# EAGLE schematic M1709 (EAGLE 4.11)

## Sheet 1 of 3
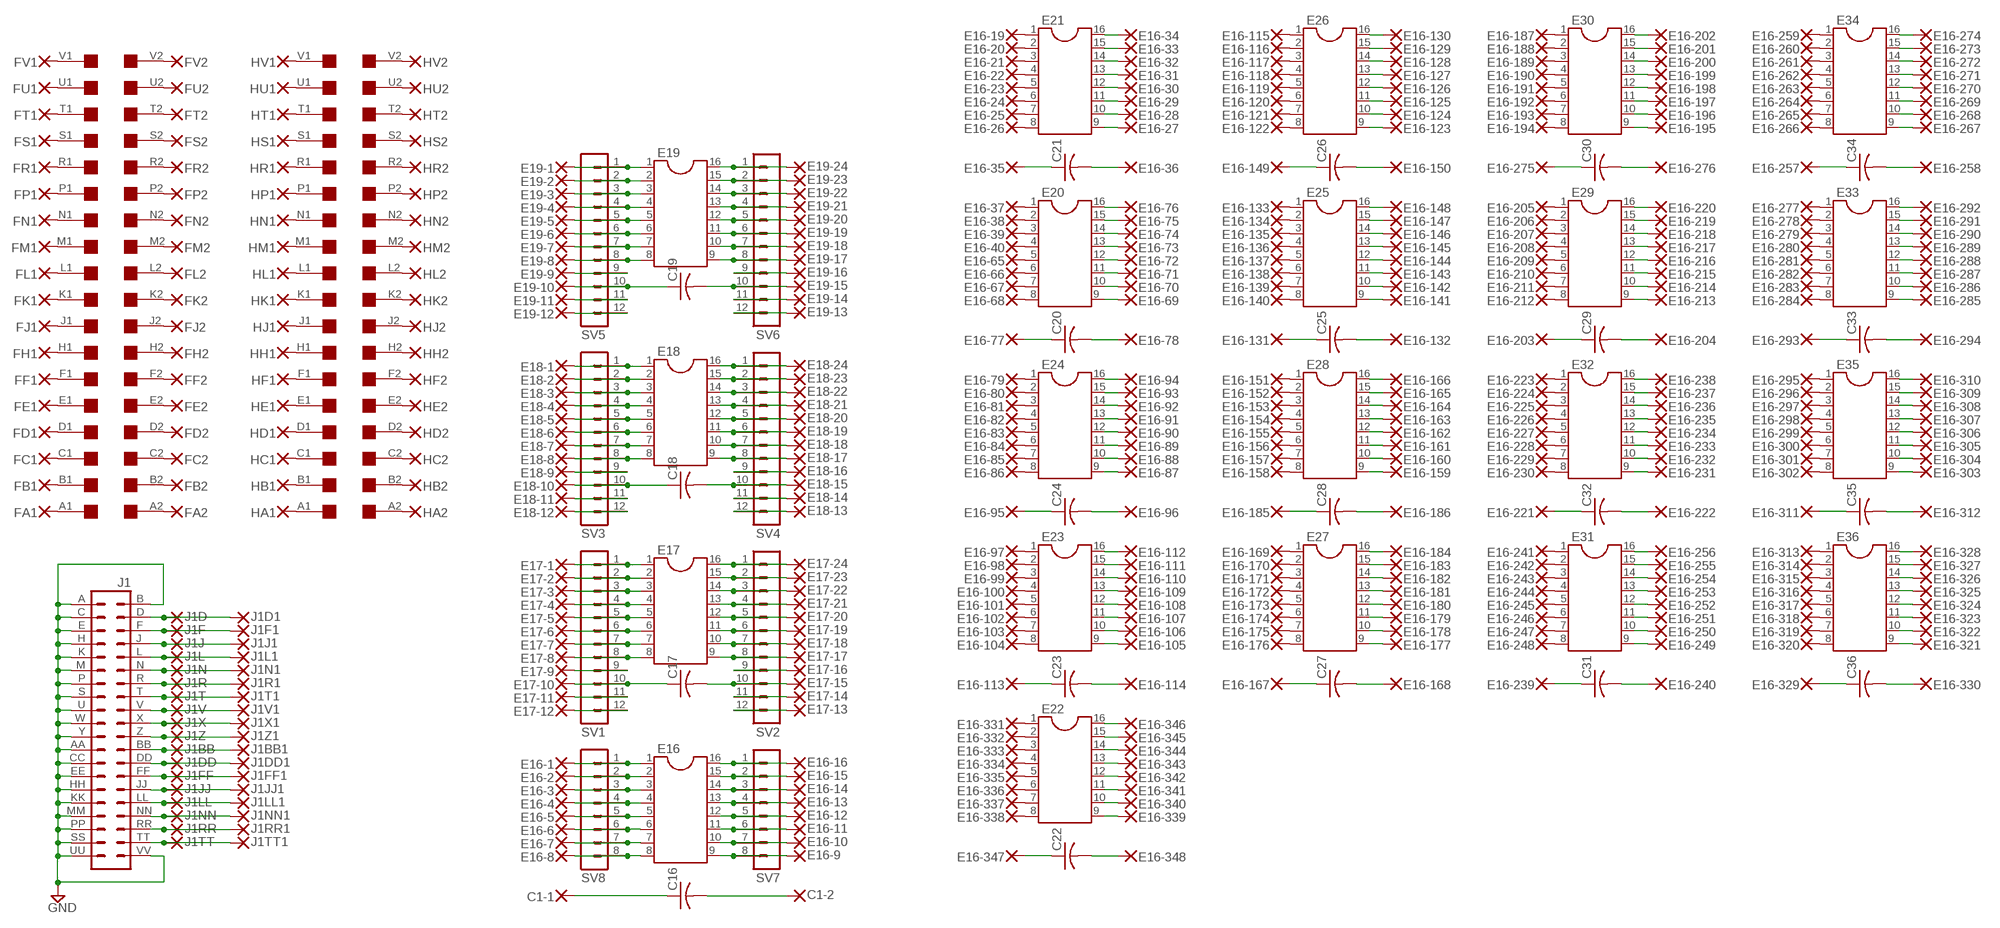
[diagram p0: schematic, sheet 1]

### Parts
C1-1  1,6/0,8  [1,6/0,8]
C1-2  1,6/0,8  [1,6/0,8]
C16  C-US075-032X103  [C075-032X103]
C17  C-US075-032X103  [C075-032X103]
C18  C-US075-032X103  [C075-032X103]
C19  C-US075-032X103  [C075-032X103]
C20  C-US075-032X103  [C075-032X103]
C21  C-US075-032X103  [C075-032X103]
C22  C-US075-032X103  [C075-032X103]
C23  C-US075-032X103  [C075-032X103]
C24  C-US075-032X103  [C075-032X103]
C25  C-US075-032X103  [C075-032X103]
C26  C-US075-032X103  [C075-032X103]
C27  C-US075-032X103  [C075-032X103]
C28  C-US075-032X103  [C075-032X103]
C29  C-US075-032X103  [C075-032X103]
C30  C-US075-032X103  [C075-032X103]
C31  C-US075-032X103  [C075-032X103]
C32  C-US075-032X103  [C075-032X103]
C33  C-US075-032X103  [C075-032X103]
C34  C-US075-032X103  [C075-032X103]
C35  C-US075-032X103  [C075-032X103]
C36  C-US075-032X103  [C075-032X103]
E16  DIL16  [DIL16]
E16-1  1,6/0,8  [1,6/0,8]
E16-2  1,6/0,8  [1,6/0,8]
E16-3  1,6/0,8  [1,6/0,8]
E16-4  1,6/0,8  [1,6/0,8]
E16-5  1,6/0,8  [1,6/0,8]
E16-6  1,6/0,8  [1,6/0,8]
E16-7  1,6/0,8  [1,6/0,8]
E16-8  1,6/0,8  [1,6/0,8]
E16-9  1,6/0,8  [1,6/0,8]
E16-10  1,6/0,8  [1,6/0,8]
E16-11  1,6/0,8  [1,6/0,8]
E16-12  1,6/0,8  [1,6/0,8]
E16-13  1,6/0,8  [1,6/0,8]
E16-14  1,6/0,8  [1,6/0,8]
E16-15  1,6/0,8  [1,6/0,8]
E16-16  1,6/0,8  [1,6/0,8]
E16-19  2,54/0,8  [2,54/0,8]
E16-20  2,54/0,8  [2,54/0,8]
E16-21  2,54/0,8  [2,54/0,8]
E16-22  2,54/0,8  [2,54/0,8]
E16-23  2,54/0,8  [2,54/0,8]
E16-24  2,54/0,8  [2,54/0,8]
E16-25  2,54/0,8  [2,54/0,8]
E16-26  2,54/0,8  [2,54/0,8]
E16-27  2,54/0,8  [2,54/0,8]
E16-28  2,54/0,8  [2,54/0,8]
E16-29  2,54/0,8  [2,54/0,8]
E16-30  2,54/0,8  [2,54/0,8]
E16-31  2,54/0,8  [2,54/0,8]
E16-32  2,54/0,8  [2,54/0,8]
E16-33  2,54/0,8  [2,54/0,8]
E16-34  2,54/0,8  [2,54/0,8]
E16-35  2,54/0,8  [2,54/0,8]
E16-36  2,54/0,8  [2,54/0,8]
E16-37  2,54/0,8  [2,54/0,8]
E16-38  2,54/0,8  [2,54/0,8]
E16-39  2,54/0,8  [2,54/0,8]
E16-40  2,54/0,8  [2,54/0,8]
E16-65  2,54/0,8  [2,54/0,8]
E16-66  2,54/0,8  [2,54/0,8]
E16-67  2,54/0,8  [2,54/0,8]
E16-68  2,54/0,8  [2,54/0,8]
E16-69  2,54/0,8  [2,54/0,8]
E16-70  2,54/0,8  [2,54/0,8]
E16-71  2,54/0,8  [2,54/0,8]
E16-72  2,54/0,8  [2,54/0,8]
E16-73  2,54/0,8  [2,54/0,8]
E16-74  2,54/0,8  [2,54/0,8]
E16-75  2,54/0,8  [2,54/0,8]
E16-76  2,54/0,8  [2,54/0,8]
E16-77  2,54/0,8  [2,54/0,8]
E16-78  2,54/0,8  [2,54/0,8]
E16-79  2,54/0,8  [2,54/0,8]
E16-80  2,54/0,8  [2,54/0,8]
E16-81  2,54/0,8  [2,54/0,8]
E16-82  2,54/0,8  [2,54/0,8]
E16-83  2,54/0,8  [2,54/0,8]
E16-84  2,54/0,8  [2,54/0,8]
E16-85  2,54/0,8  [2,54/0,8]
E16-86  2,54/0,8  [2,54/0,8]
E16-87  2,54/0,8  [2,54/0,8]
E16-88  2,54/0,8  [2,54/0,8]
E16-89  2,54/0,8  [2,54/0,8]
E16-90  2,54/0,8  [2,54/0,8]
E16-91  2,54/0,8  [2,54/0,8]
E16-92  2,54/0,8  [2,54/0,8]
E16-93  2,54/0,8  [2,54/0,8]
E16-94  2,54/0,8  [2,54/0,8]
E16-95  2,54/0,8  [2,54/0,8]
E16-96  2,54/0,8  [2,54/0,8]
E16-97  2,54/0,8  [2,54/0,8]
E16-98  2,54/0,8  [2,54/0,8]
E16-99  2,54/0,8  [2,54/0,8]
E16-100  2,54/0,8  [2,54/0,8]
E16-101  2,54/0,8  [2,54/0,8]
E16-102  2,54/0,8  [2,54/0,8]
E16-103  2,54/0,8  [2,54/0,8]
E16-104  2,54/0,8  [2,54/0,8]
E16-105  2,54/0,8  [2,54/0,8]
E16-106  2,54/0,8  [2,54/0,8]
E16-107  2,54/0,8  [2,54/0,8]
E16-108  2,54/0,8  [2,54/0,8]
E16-109  2,54/0,8  [2,54/0,8]
E16-110  2,54/0,8  [2,54/0,8]
E16-111  2,54/0,8  [2,54/0,8]
E16-112  2,54/0,8  [2,54/0,8]
E16-113  2,54/0,8  [2,54/0,8]
E16-114  2,54/0,8  [2,54/0,8]
E16-115  2,54/0,8  [2,54/0,8]
E16-116  2,54/0,8  [2,54/0,8]
E16-117  2,54/0,8  [2,54/0,8]
E16-118  2,54/0,8  [2,54/0,8]
E16-119  2,54/0,8  [2,54/0,8]
E16-120  2,54/0,8  [2,54/0,8]
E16-121  2,54/0,8  [2,54/0,8]
E16-122  2,54/0,8  [2,54/0,8]
E16-123  2,54/0,8  [2,54/0,8]
E16-124  2,54/0,8  [2,54/0,8]
E16-125  2,54/0,8  [2,54/0,8]
E16-126  2,54/0,8  [2,54/0,8]
E16-127  2,54/0,8  [2,54/0,8]
E16-128  2,54/0,8  [2,54/0,8]
E16-129  2,54/0,8  [2,54/0,8]
E16-130  2,54/0,8  [2,54/0,8]
E16-131  2,54/0,8  [2,54/0,8]
E16-132  2,54/0,8  [2,54/0,8]
E16-133  2,54/0,8  [2,54/0,8]
E16-134  2,54/0,8  [2,54/0,8]
E16-135  2,54/0,8  [2,54/0,8]
E16-136  2,54/0,8  [2,54/0,8]
E16-137  2,54/0,8  [2,54/0,8]
E16-138  2,54/0,8  [2,54/0,8]
E16-139  2,54/0,8  [2,54/0,8]
E16-140  2,54/0,8  [2,54/0,8]
E16-141  2,54/0,8  [2,54/0,8]
E16-142  2,54/0,8  [2,54/0,8]
E16-143  2,54/0,8  [2,54/0,8]
E16-144  2,54/0,8  [2,54/0,8]
E16-145  2,54/0,8  [2,54/0,8]
E16-146  2,54/0,8  [2,54/0,8]
E16-147  2,54/0,8  [2,54/0,8]
E16-148  2,54/0,8  [2,54/0,8]
E16-149  2,54/0,8  [2,54/0,8]
E16-150  2,54/0,8  [2,54/0,8]
E16-151  2,54/0,8  [2,54/0,8]
E16-152  2,54/0,8  [2,54/0,8]
E16-153  2,54/0,8  [2,54/0,8]
E16-154  2,54/0,8  [2,54/0,8]
E16-155  2,54/0,8  [2,54/0,8]
E16-156  2,54/0,8  [2,54/0,8]
E16-157  2,54/0,8  [2,54/0,8]
E16-158  2,54/0,8  [2,54/0,8]
E16-159  2,54/0,8  [2,54/0,8]
E16-160  2,54/0,8  [2,54/0,8]
E16-161  2,54/0,8  [2,54/0,8]
E16-162  2,54/0,8  [2,54/0,8]
E16-163  2,54/0,8  [2,54/0,8]
E16-164  2,54/0,8  [2,54/0,8]
E16-165  2,54/0,8  [2,54/0,8]
E16-166  2,54/0,8  [2,54/0,8]
E16-167  2,54/0,8  [2,54/0,8]
E16-168  2,54/0,8  [2,54/0,8]
E16-169  2,54/0,8  [2,54/0,8]
E16-170  2,54/0,8  [2,54/0,8]
E16-171  2,54/0,8  [2,54/0,8]
E16-172  2,54/0,8  [2,54/0,8]
E16-173  2,54/0,8  [2,54/0,8]
E16-174  2,54/0,8  [2,54/0,8]
E16-175  2,54/0,8  [2,54/0,8]
E16-176  2,54/0,8  [2,54/0,8]
E16-177  2,54/0,8  [2,54/0,8]
E16-178  2,54/0,8  [2,54/0,8]
E16-179  2,54/0,8  [2,54/0,8]
E16-180  2,54/0,8  [2,54/0,8]
E16-181  2,54/0,8  [2,54/0,8]
E16-182  2,54/0,8  [2,54/0,8]
E16-183  2,54/0,8  [2,54/0,8]
E16-184  2,54/0,8  [2,54/0,8]
E16-185  2,54/0,8  [2,54/0,8]
E16-186  2,54/0,8  [2,54/0,8]
E16-187  2,54/0,8  [2,54/0,8]
E16-188  2,54/0,8  [2,54/0,8]
E16-189  2,54/0,8  [2,54/0,8]
E16-190  2,54/0,8  [2,54/0,8]
E16-191  2,54/0,8  [2,54/0,8]
E16-192  2,54/0,8  [2,54/0,8]
E16-193  2,54/0,8  [2,54/0,8]
E16-194  2,54/0,8  [2,54/0,8]
E16-195  2,54/0,8  [2,54/0,8]
E16-196  2,54/0,8  [2,54/0,8]
E16-197  2,54/0,8  [2,54/0,8]
E16-198  2,54/0,8  [2,54/0,8]
E16-199  2,54/0,8  [2,54/0,8]
E16-200  2,54/0,8  [2,54/0,8]
E16-201  2,54/0,8  [2,54/0,8]
E16-202  2,54/0,8  [2,54/0,8]
E16-203  2,54/0,8  [2,54/0,8]
E16-204  2,54/0,8  [2,54/0,8]
E16-205  2,54/0,8  [2,54/0,8]
E16-206  2,54/0,8  [2,54/0,8]
E16-207  2,54/0,8  [2,54/0,8]
E16-208  2,54/0,8  [2,54/0,8]
E16-209  2,54/0,8  [2,54/0,8]
E16-210  2,54/0,8  [2,54/0,8]
E16-211  2,54/0,8  [2,54/0,8]
E16-212  2,54/0,8  [2,54/0,8]
E16-213  2,54/0,8  [2,54/0,8]
E16-214  2,54/0,8  [2,54/0,8]
E16-215  2,54/0,8  [2,54/0,8]
E16-216  2,54/0,8  [2,54/0,8]
E16-217  2,54/0,8  [2,54/0,8]
E16-218  2,54/0,8  [2,54/0,8]
E16-219  2,54/0,8  [2,54/0,8]
E16-220  2,54/0,8  [2,54/0,8]
E16-221  2,54/0,8  [2,54/0,8]
E16-222  2,54/0,8  [2,54/0,8]
E16-223  2,54/0,8  [2,54/0,8]
E16-224  2,54/0,8  [2,54/0,8]
E16-225  2,54/0,8  [2,54/0,8]
E16-226  2,54/0,8  [2,54/0,8]
E16-227  2,54/0,8  [2,54/0,8]
E16-228  2,54/0,8  [2,54/0,8]
E16-229  2,54/0,8  [2,54/0,8]
E16-230  2,54/0,8  [2,54/0,8]
E16-231  2,54/0,8  [2,54/0,8]
E16-232  2,54/0,8  [2,54/0,8]
E16-233  2,54/0,8  [2,54/0,8]
E16-234  2,54/0,8  [2,54/0,8]
E16-235  2,54/0,8  [2,54/0,8]
E16-236  2,54/0,8  [2,54/0,8]
E16-237  2,54/0,8  [2,54/0,8]
E16-238  2,54/0,8  [2,54/0,8]
E16-239  2,54/0,8  [2,54/0,8]
E16-240  2,54/0,8  [2,54/0,8]
E16-241  2,54/0,8  [2,54/0,8]
E16-242  2,54/0,8  [2,54/0,8]
E16-243  2,54/0,8  [2,54/0,8]
E16-244  2,54/0,8  [2,54/0,8]
E16-245  2,54/0,8  [2,54/0,8]
E16-246  2,54/0,8  [2,54/0,8]
E16-247  2,54/0,8  [2,54/0,8]
E16-248  2,54/0,8  [2,54/0,8]
E16-249  2,54/0,8  [2,54/0,8]
E16-250  2,54/0,8  [2,54/0,8]
E16-251  2,54/0,8  [2,54/0,8]
E16-252  2,54/0,8  [2,54/0,8]
E16-253  2,54/0,8  [2,54/0,8]
E16-254  2,54/0,8  [2,54/0,8]
E16-255  2,54/0,8  [2,54/0,8]
E16-256  2,54/0,8  [2,54/0,8]
E16-257  2,54/0,8  [2,54/0,8]
E16-258  2,54/0,8  [2,54/0,8]
E16-259  2,54/0,8  [2,54/0,8]
E16-260  2,54/0,8  [2,54/0,8]
E16-261  2,54/0,8  [2,54/0,8]
E16-262  2,54/0,8  [2,54/0,8]
E16-263  2,54/0,8  [2,54/0,8]
E16-264  2,54/0,8  [2,54/0,8]
E16-265  2,54/0,8  [2,54/0,8]
E16-266  2,54/0,8  [2,54/0,8]
E16-267  2,54/0,8  [2,54/0,8]
E16-268  2,54/0,8  [2,54/0,8]
E16-269  2,54/0,8  [2,54/0,8]
E16-270  2,54/0,8  [2,54/0,8]
E16-271  2,54/0,8  [2,54/0,8]
E16-272  2,54/0,8  [2,54/0,8]
E16-273  2,54/0,8  [2,54/0,8]
E16-274  2,54/0,8  [2,54/0,8]
E16-275  2,54/0,8  [2,54/0,8]
E16-276  2,54/0,8  [2,54/0,8]
E16-277  2,54/0,8  [2,54/0,8]
E16-278  2,54/0,8  [2,54/0,8]
E16-279  2,54/0,8  [2,54/0,8]
E16-280  2,54/0,8  [2,54/0,8]
E16-281  2,54/0,8  [2,54/0,8]
E16-282  2,54/0,8  [2,54/0,8]
E16-283  2,54/0,8  [2,54/0,8]
E16-284  2,54/0,8  [2,54/0,8]
E16-285  2,54/0,8  [2,54/0,8]
E16-286  2,54/0,8  [2,54/0,8]
E16-287  2,54/0,8  [2,54/0,8]
E16-288  2,54/0,8  [2,54/0,8]
E16-289  2,54/0,8  [2,54/0,8]
E16-290  2,54/0,8  [2,54/0,8]
E16-291  2,54/0,8  [2,54/0,8]
E16-292  2,54/0,8  [2,54/0,8]
E16-293  2,54/0,8  [2,54/0,8]
E16-294  2,54/0,8  [2,54/0,8]
E16-295  2,54/0,8  [2,54/0,8]
E16-296  2,54/0,8  [2,54/0,8]
E16-297  2,54/0,8  [2,54/0,8]
E16-298  2,54/0,8  [2,54/0,8]
E16-299  2,54/0,8  [2,54/0,8]
E16-300  2,54/0,8  [2,54/0,8]
E16-301  2,54/0,8  [2,54/0,8]
E16-302  2,54/0,8  [2,54/0,8]
E16-303  2,54/0,8  [2,54/0,8]
E16-304  2,54/0,8  [2,54/0,8]
E16-305  2,54/0,8  [2,54/0,8]
E16-306  2,54/0,8  [2,54/0,8]
E16-307  2,54/0,8  [2,54/0,8]
E16-308  2,54/0,8  [2,54/0,8]
E16-309  2,54/0,8  [2,54/0,8]
E16-310  2,54/0,8  [2,54/0,8]
E16-311  2,54/0,8  [2,54/0,8]
E16-312  2,54/0,8  [2,54/0,8]
E16-313  2,54/0,8  [2,54/0,8]
E16-314  2,54/0,8  [2,54/0,8]
E16-315  2,54/0,8  [2,54/0,8]
E16-316  2,54/0,8  [2,54/0,8]
E16-317  2,54/0,8  [2,54/0,8]
E16-318  2,54/0,8  [2,54/0,8]
E16-319  2,54/0,8  [2,54/0,8]
E16-320  2,54/0,8  [2,54/0,8]
E16-321  2,54/0,8  [2,54/0,8]
E16-322  2,54/0,8  [2,54/0,8]
E16-323  2,54/0,8  [2,54/0,8]
E16-324  2,54/0,8  [2,54/0,8]
E16-325  2,54/0,8  [2,54/0,8]
E16-326  2,54/0,8  [2,54/0,8]
E16-327  2,54/0,8  [2,54/0,8]
E16-328  2,54/0,8  [2,54/0,8]
E16-329  2,54/0,8  [2,54/0,8]
E16-330  2,54/0,8  [2,54/0,8]
E16-331  2,54/0,8  [2,54/0,8]
E16-332  2,54/0,8  [2,54/0,8]
E16-333  2,54/0,8  [2,54/0,8]
E16-334  2,54/0,8  [2,54/0,8]
E16-335  2,54/0,8  [2,54/0,8]
E16-336  2,54/0,8  [2,54/0,8]
E16-337  2,54/0,8  [2,54/0,8]
E16-338  2,54/0,8  [2,54/0,8]
E16-339  2,54/0,8  [2,54/0,8]
E16-340  2,54/0,8  [2,54/0,8]
E16-341  2,54/0,8  [2,54/0,8]
E16-342  2,54/0,8  [2,54/0,8]
E16-343  2,54/0,8  [2,54/0,8]
E16-344  2,54/0,8  [2,54/0,8]
E16-345  2,54/0,8  [2,54/0,8]
E16-346  2,54/0,8  [2,54/0,8]
E16-347  2,54/0,8  [2,54/0,8]
E16-348  2,54/0,8  [2,54/0,8]
E17  DIL16  [DIL16]
E17-1  1,6/0,8  [1,6/0,8]
E17-2  1,6/0,8  [1,6/0,8]
E17-3  1,6/0,8  [1,6/0,8]
E17-4  1,6/0,8  [1,6/0,8]
E17-5  1,6/0,8  [1,6/0,8]
E17-6  1,6/0,8  [1,6/0,8]
E17-7  1,6/0,8  [1,6/0,8]
E17-8  1,6/0,8  [1,6/0,8]
E17-9  1,6/0,8  [1,6/0,8]
E17-10  1,6/0,8  [1,6/0,8]
E17-11  1,6/0,8  [1,6/0,8]
E17-12  1,6/0,8  [1,6/0,8]
E17-13  1,6/0,8  [1,6/0,8]
E17-14  1,6/0,8  [1,6/0,8]
E17-15  1,6/0,8  [1,6/0,8]
E17-16  1,6/0,8  [1,6/0,8]
E17-17  1,6/0,8  [1,6/0,8]
E17-18  1,6/0,8  [1,6/0,8]
E17-19  1,6/0,8  [1,6/0,8]
E17-20  1,6/0,8  [1,6/0,8]
E17-21  1,6/0,8  [1,6/0,8]
E17-22  1,6/0,8  [1,6/0,8]
E17-23  1,6/0,8  [1,6/0,8]
E17-24  1,6/0,8  [1,6/0,8]
E18  DIL16  [DIL16]
E18-1  1,6/0,8  [1,6/0,8]
E18-2  1,6/0,8  [1,6/0,8]
E18-3  1,6/0,8  [1,6/0,8]
E18-4  1,6/0,8  [1,6/0,8]
E18-5  1,6/0,8  [1,6/0,8]
E18-6  1,6/0,8  [1,6/0,8]
E18-7  1,6/0,8  [1,6/0,8]
E18-8  1,6/0,8  [1,6/0,8]
E18-9  1,6/0,8  [1,6/0,8]
E18-10  1,6/0,8  [1,6/0,8]
E18-11  1,6/0,8  [1,6/0,8]
E18-12  1,6/0,8  [1,6/0,8]
E18-13  1,6/0,8  [1,6/0,8]
E18-14  1,6/0,8  [1,6/0,8]
E18-15  1,6/0,8  [1,6/0,8]
E18-16  1,6/0,8  [1,6/0,8]
E18-17  1,6/0,8  [1,6/0,8]
E18-18  1,6/0,8  [1,6/0,8]
E18-19  1,6/0,8  [1,6/0,8]
E18-20  1,6/0,8  [1,6/0,8]
E18-21  1,6/0,8  [1,6/0,8]
E18-22  1,6/0,8  [1,6/0,8]
E18-23  1,6/0,8  [1,6/0,8]
E18-24  1,6/0,8  [1,6/0,8]
E19  DIL16  [DIL16]
E19-1  1,6/0,8  [1,6/0,8]
E19-2  1,6/0,8  [1,6/0,8]
E19-3  1,6/0,8  [1,6/0,8]
E19-4  1,6/0,8  [1,6/0,8]
E19-5  1,6/0,8  [1,6/0,8]
E19-6  1,6/0,8  [1,6/0,8]
E19-7  1,6/0,8  [1,6/0,8]
E19-8  1,6/0,8  [1,6/0,8]
E19-9  1,6/0,8  [1,6/0,8]
E19-10  1,6/0,8  [1,6/0,8]
E19-11  1,6/0,8  [1,6/0,8]
E19-12  1,6/0,8  [1,6/0,8]
E19-13  1,6/0,8  [1,6/0,8]
E19-14  1,6/0,8  [1,6/0,8]
E19-15  1,6/0,8  [1,6/0,8]
E19-16  1,6/0,8  [1,6/0,8]
E19-17  1,6/0,8  [1,6/0,8]
E19-18  1,6/0,8  [1,6/0,8]
E19-19  1,6/0,8  [1,6/0,8]
E19-20  1,6/0,8  [1,6/0,8]
E19-21  1,6/0,8  [1,6/0,8]
E19-22  1,6/0,8  [1,6/0,8]
E19-23  1,6/0,8  [1,6/0,8]
E19-24  1,6/0,8  [1,6/0,8]
E20  DIL16  [DIL16]
E21  DIL16  [DIL16]
E22  DIL16  [DIL16]
E23  DIL16  [DIL16]
E24  DIL16  [DIL16]
E25  DIL16  [DIL16]
E26  DIL16  [DIL16]
E27  DIL16  [DIL16]
E28  DIL16  [DIL16]
E29  DIL16  [DIL16]
E30  DIL16  [DIL16]
E31  DIL16  [DIL16]
E32  DIL16  [DIL16]
E33  DIL16  [DIL16]
E34  DIL16  [DIL16]
E35  DIL16  [DIL16]
E36  DIL16  [DIL16]
F  SINGLE  [EDGE-CON2]
FA1  2,54/0,8  [2,54/0,8]
FA2  2,54/0,8  [2,54/0,8]
FB1  2,54/0,8  [2,54/0,8]
FB2  2,54/0,8  [2,54/0,8]
FC1  2,54/0,8  [2,54/0,8]
FC2  2,54/0,8  [2,54/0,8]
FD1  2,54/0,8  [2,54/0,8]
FD2  2,54/0,8  [2,54/0,8]
FE1  2,54/0,8  [2,54/0,8]
FE2  2,54/0,8  [2,54/0,8]
FF1  2,54/0,8  [2,54/0,8]
FF2  2,54/0,8  [2,54/0,8]
FH1  2,54/0,8  [2,54/0,8]
FH2  2,54/0,8  [2,54/0,8]
FJ1  2,54/0,8  [2,54/0,8]
FJ2  2,54/0,8  [2,54/0,8]
FK1  2,54/0,8  [2,54/0,8]
FK2  2,54/0,8  [2,54/0,8]
FL1  2,54/0,8  [2,54/0,8]
FL2  2,54/0,8  [2,54/0,8]
FM1  2,54/0,8  [2,54/0,8]
FM2  2,54/0,8  [2,54/0,8]
FN1  2,54/0,8  [2,54/0,8]
FN2  2,54/0,8  [2,54/0,8]
FP1  2,54/0,8  [2,54/0,8]
FP2  2,54/0,8  [2,54/0,8]
FR1  2,54/0,8  [2,54/0,8]
FR2  2,54/0,8  [2,54/0,8]
FS1  2,54/0,8  [2,54/0,8]
FS2  2,54/0,8  [2,54/0,8]
FT1  2,54/0,8  [2,54/0,8]
FT2  2,54/0,8  [2,54/0,8]
FU1  2,54/0,8  [2,54/0,8]
FU2  2,54/0,8  [2,54/0,8]
FV1  2,54/0,8  [2,54/0,8]
FV2  2,54/0,8  [2,54/0,8]
H  SINGLE  [EDGE-CON2]
HA1  2,54/0,8  [2,54/0,8]
HA2  2,54/0,8  [2,54/0,8]
HB1  2,54/0,8  [2,54/0,8]
HB2  2,54/0,8  [2,54/0,8]
HC1  2,54/0,8  [2,54/0,8]
HC2  2,54/0,8  [2,54/0,8]
HD1  2,54/0,8  [2,54/0,8]
HD2  2,54/0,8  [2,54/0,8]
HE1  2,54/0,8  [2,54/0,8]
HE2  2,54/0,8  [2,54/0,8]
HF1  2,54/0,8  [2,54/0,8]
HF2  2,54/0,8  [2,54/0,8]
HH1  2,54/0,8  [2,54/0,8]
HH2  2,54/0,8  [2,54/0,8]
HJ1  2,54/0,8  [2,54/0,8]
HJ2  2,54/0,8  [2,54/0,8]
HK1  2,54/0,8  [2,54/0,8]
HK2  2,54/0,8  [2,54/0,8]
HL1  2,54/0,8  [2,54/0,8]
HL2  2,54/0,8  [2,54/0,8]
HM1  2,54/0,8  [2,54/0,8]
HM2  2,54/0,8  [2,54/0,8]
HN1  2,54/0,8  [2,54/0,8]
HN2  2,54/0,8  [2,54/0,8]
HP1  2,54/0,8  [2,54/0,8]
HP2  2,54/0,8  [2,54/0,8]
HR1  2,54/0,8  [2,54/0,8]
HR2  2,54/0,8  [2,54/0,8]
HS1  2,54/0,8  [2,54/0,8]
HS2  2,54/0,8  [2,54/0,8]
HT1  2,54/0,8  [2,54/0,8]
HT2  2,54/0,8  [2,54/0,8]
HU1  2,54/0,8  [2,54/0,8]
HU2  2,54/0,8  [2,54/0,8]
HV1  2,54/0,8  [2,54/0,8]
HV2  2,54/0,8  [2,54/0,8]
J1  DEC40PINH  [DEC40PINH]
J1BB  2,54/0,8  [2,54/0,8]
J1BB1  2,54/0,8  [2,54/0,8]
J1D  2,54/0,8  [2,54/0,8]
J1D1  2,54/0,8  [2,54/0,8]
J1DD  2,54/0,8  [2,54/0,8]
J1DD1  2,54/0,8  [2,54/0,8]
J1F  2,54/0,8  [2,54/0,8]
J1F1  2,54/0,8  [2,54/0,8]
J1FF  2,54/0,8  [2,54/0,8]
J1FF1  2,54/0,8  [2,54/0,8]
J1J  2,54/0,8  [2,54/0,8]
J1J1  2,54/0,8  [2,54/0,8]
J1JJ  2,54/0,8  [2,54/0,8]
J1JJ1  2,54/0,8  [2,54/0,8]
J1L  2,54/0,8  [2,54/0,8]
J1L1  2,54/0,8  [2,54/0,8]
J1LL  2,54/0,8  [2,54/0,8]
J1LL1  2,54/0,8  [2,54/0,8]
J1N  2,54/0,8  [2,54/0,8]
J1N1  2,54/0,8  [2,54/0,8]
J1NN  2,54/0,8  [2,54/0,8]
J1NN1  2,54/0,8  [2,54/0,8]
J1R  2,54/0,8  [2,54/0,8]
J1R1  2,54/0,8  [2,54/0,8]
J1RR  2,54/0,8  [2,54/0,8]
J1RR1  2,54/0,8  [2,54/0,8]
J1T  2,54/0,8  [2,54/0,8]
J1T1  2,54/0,8  [2,54/0,8]
J1TT  2,54/0,8  [2,54/0,8]
J1TT1  2,54/0,8  [2,54/0,8]
J1V  2,54/0,8  [2,54/0,8]
J1V1  2,54/0,8  [2,54/0,8]
J1X  2,54/0,8  [2,54/0,8]
J1X1  2,54/0,8  [2,54/0,8]
J1Z  2,54/0,8  [2,54/0,8]
J1Z1  2,54/0,8  [2,54/0,8]
SV1  MA12-1  [MA12-1]
SV2  MA12-1  [MA12-1]
SV3  MA12-1  [MA12-1]
SV4  MA12-1  [MA12-1]
SV5  MA12-1  [MA12-1]
SV6  MA12-1  [MA12-1]
SV7  MA08-1  [MA08-1]
SV8  MA08-1  [MA08-1]

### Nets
GND: J1.A J1.AA J1.B J1.C J1.CC J1.E J1.EE J1.H J1.HH J1.K J1.KK J1.M J1.MM J1.P J1.PP J1.S J1.SS J1.U J1.UU J1.VV J1.W J1.Y ; also sheet 2,3
N$1: J1.D J1D1.1(P) J1D.1(P)
N$2: J1.F J1F1.1(P) J1F.1(P)
N$3: J1.J J1J1.1(P) J1J.1(P)
N$4: J1.L J1L1.1(P) J1L.1(P)
N$5: J1.N J1N1.1(P) J1N.1(P)
N$6: J1.R J1R1.1(P) J1R.1(P)
N$7: J1.T J1T1.1(P) J1T.1(P)
N$8: J1.V J1V1.1(P) J1V.1(P)
N$9: J1.X J1X1.1(P) J1X.1(P)
N$10: J1.Z J1Z1.1(P) J1Z.1(P)
N$11: J1.BB J1BB1.1(P) J1BB.1(P)
N$12: J1.DD J1DD1.1(P) J1DD.1(P)
N$13: J1.FF J1FF1.1(P) J1FF.1(P)
N$14: J1.JJ J1JJ1.1(P) J1JJ.1(P)
N$15: J1.LL J1LL1.1(P) J1LL.1(P)
N$16: J1.NN J1NN1.1(P) J1NN.1(P)
N$17: J1.RR J1RR1.1(P) J1RR.1(P)
N$18: J1.TT J1TT1.1(P) J1TT.1(P)
N$19: F.A1 FA1.1(P)
N$20: F.B1 FB1.1(P)
N$21: F.C1 FC1.1(P)
N$22: F.D1 FD1.1(P)
N$23: F.E1 FE1.1(P)
N$24: F.F1 FF1.1(P)
N$25: F.H1 FH1.1(P)
N$26: F.J1 FJ1.1(P)
N$27: F.K1 FK1.1(P)
N$28: F.L1 FL1.1(P)
N$29: F.M1 FM1.1(P)
N$30: F.N1 FN1.1(P)
N$31: F.P1 FP1.1(P)
N$32: F.R1 FR1.1(P)
N$33: F.S1 FS1.1(P)
N$34: F.T1 FT1.1(P)
N$35: F.U1 FU1.1(P)
N$36: F.V1 FV1.1(P)
N$37: F.A2 FA2.1(P)
N$38: F.B2 FB2.1(P)
N$39: F.C2 FC2.1(P)
N$40: F.D2 FD2.1(P)
N$41: F.E2 FE2.1(P)
N$42: F.F2 FF2.1(P)
N$43: F.H2 FH2.1(P)
N$44: F.J2 FJ2.1(P)
N$45: F.K2 FK2.1(P)
N$46: F.L2 FL2.1(P)
N$47: F.M2 FM2.1(P)
N$48: F.N2 FN2.1(P)
N$49: F.P2 FP2.1(P)
N$50: F.R2 FR2.1(P)
N$51: F.S2 FS2.1(P)
N$52: F.T2 FT2.1(P)
N$53: F.U2 FU2.1(P)
N$54: F.V2 FV2.1(P)
N$55: H.A2 HA2.1(P)
N$56: H.B2 HB2.1(P)
N$57: H.C2 HC2.1(P)
N$58: H.D2 HD2.1(P)
N$59: H.E2 HE2.1(P)
N$60: H.F2 HF2.1(P)
N$61: H.H2 HH2.1(P)
N$62: H.J2 HJ2.1(P)
N$63: H.K2 HK2.1(P)
N$64: H.L2 HL2.1(P)
N$65: H.M2 HM2.1(P)
N$66: H.N2 HN2.1(P)
N$67: H.P2 HP2.1(P)
N$68: H.R2 HR2.1(P)
N$69: H.S2 HS2.1(P)
N$70: H.T2 HT2.1(P)
N$71: H.U2 HU2.1(P)
N$72: H.V2 HV2.1(P)
N$73: H.A1 HA1.1(P)
N$74: H.B1 HB1.1(P)
N$75: H.C1 HC1.1(P)
N$76: H.D1 HD1.1(P)
N$77: H.E1 HE1.1(P)
N$78: H.F1 HF1.1(P)
N$79: H.H1 HH1.1(P)
N$80: H.J1 HJ1.1(P)
N$81: H.K1 HK1.1(P)
N$82: H.L1 HL1.1(P)
N$83: H.M1 HM1.1(P)
N$84: H.N1 HN1.1(P)
N$85: H.P1 HP1.1(P)
N$86: H.R1 HR1.1(P)
N$87: H.S1 HS1.1(P)
N$88: H.T1 HT1.1(P)
N$89: H.U1 HU1.1(P)
N$90: H.V1 HV1.1(P)
N$91: E17-1.1(P) E17.1 SV1.1
N$92: E17-2.1(P) E17.2 SV1.2
N$93: E17-3.1(P) E17.3 SV1.3
N$94: E17-4.1(P) E17.4 SV1.4
N$95: E17-5.1(P) E17.5 SV1.5
N$96: E17-6.1(P) E17.6 SV1.6
N$97: E17-7.1(P) E17.7 SV1.7
N$98: E17-8.1(P) E17.8 SV1.8
N$99: E17-9.1(P) SV1.9
N$100: C17.1 E17-10.1(P) SV1.10
N$101: C17.2 E17-15.1(P) SV2.10
N$102: E17-16.1(P) SV2.9
N$103: E17-17.1(P) E17.9 SV2.8
N$104: E17-18.1(P) E17.10 SV2.7
N$105: E17-19.1(P) E17.11 SV2.6
N$106: E17-20.1(P) E17.12 SV2.5
N$107: E17-21.1(P) E17.13 SV2.4
N$108: E17-22.1(P) E17.14 SV2.3
N$109: E17-23.1(P) E17.15 SV2.2
N$110: E17-24.1(P) E17.16 SV2.1
N$111: E18-11.1(P) SV3.11
N$112: E18-12.1(P) SV3.12
N$113: E18-13.1(P) SV4.12
N$114: E18-14.1(P) SV4.11
N$115: E18-1.1(P) E18.1 SV3.1
N$116: E18-2.1(P) E18.2 SV3.2
N$117: E17-11.1(P) SV1.11
N$118: E17-12.1(P) SV1.12
N$119: E16-1.1(P) E16.1 SV8.1
N$120: E16-2.1(P) E16.2 SV8.2
N$121: E16-3.1(P) E16.3 SV8.3
N$122: E16-4.1(P) E16.4 SV8.4
N$123: E16-5.1(P) E16.5 SV8.5
N$124: E16-6.1(P) E16.6 SV8.6
N$125: E16-7.1(P) E16.7 SV8.7
N$126: E16-8.1(P) E16.8 SV8.8
N$127: E16-9.1(P) E16.9 SV7.8
N$128: E16-10.1(P) E16.10 SV7.7
N$129: E16-11.1(P) E16.11 SV7.6
N$130: E16-12.1(P) E16.12 SV7.5
N$131: E16-13.1(P) E16.13 SV7.4
N$132: E16-14.1(P) E16.14 SV7.3
N$133: E16-15.1(P) E16.15 SV7.2
N$134: E16-16.1(P) E16.16 SV7.1
N$135: E17-13.1(P) SV2.12
N$136: E17-14.1(P) SV2.11
N$137: E18-3.1(P) E18.3 SV3.3
N$138: E18-4.1(P) E18.4 SV3.4
N$139: E18-5.1(P) E18.5 SV3.5
N$140: E18-6.1(P) E18.6 SV3.6
N$141: E18-7.1(P) E18.7 SV3.7
N$142: E18-8.1(P) E18.8 SV3.8
N$143: E18-9.1(P) SV3.9
N$144: C18.1 E18-10.1(P) SV3.10
N$145: C18.2 E18-15.1(P) SV4.10
N$146: E18-16.1(P) SV4.9
N$147: E18-17.1(P) E18.9 SV4.8
N$148: E18-18.1(P) E18.10 SV4.7
N$149: E18-19.1(P) E18.11 SV4.6
N$150: E18-20.1(P) E18.12 SV4.5
N$151: E18-21.1(P) E18.13 SV4.4
N$152: E18-22.1(P) E18.14 SV4.3
N$153: E18-23.1(P) E18.15 SV4.2
N$154: E18-24.1(P) E18.16 SV4.1
N$155: E19-11.1(P) SV5.11
N$156: E19-12.1(P) SV5.12
N$157: E19-13.1(P) SV6.12
N$158: E19-14.1(P) SV6.11
N$159: E19-1.1(P) E19.1 SV5.1
N$160: E19-2.1(P) E19.2 SV5.2
N$161: E19-3.1(P) E19.3 SV5.3
N$162: E19-4.1(P) E19.4 SV5.4
N$163: E19-5.1(P) E19.5 SV5.5
N$164: E19-6.1(P) E19.6 SV5.6
N$165: E19-7.1(P) E19.7 SV5.7
N$166: E19-8.1(P) E19.8 SV5.8
N$167: E19-9.1(P) SV5.9
N$168: C19.1 E19-10.1(P) SV5.10
N$169: C19.2 E19-15.1(P) SV6.10
N$170: E19-16.1(P) SV6.9
N$171: E19-17.1(P) E19.9 SV6.8
N$172: E19-18.1(P) E19.10 SV6.7
N$173: E19-19.1(P) E19.11 SV6.6
N$174: E19-20.1(P) E19.12 SV6.5
N$175: E19-21.1(P) E19.13 SV6.4
N$176: E19-22.1(P) E19.14 SV6.3
N$177: E19-23.1(P) E19.15 SV6.2
N$178: E19-24.1(P) E19.16 SV6.1
N$179: C1-1.1(P) C16.1
N$180: C1-2.1(P) C16.2
N$181: E16-19.1(P) E21.1
N$182: E16-20.1(P) E21.2
N$183: E16-21.1(P) E21.3
N$184: E16-22.1(P) E21.4
N$185: E16-23.1(P) E21.5
N$186: E16-24.1(P) E21.6
N$187: E16-25.1(P) E21.7
N$188: E16-26.1(P) E21.8
N$189: E16-27.1(P) E21.9
N$190: E16-28.1(P) E21.10
N$191: E16-29.1(P) E21.11
N$192: E16-30.1(P) E21.12
N$193: E16-31.1(P) E21.13
N$194: E16-32.1(P) E21.14
N$195: E16-33.1(P) E21.15
N$196: E16-34.1(P) E21.16
N$197: C21.1 E16-35.1(P)
N$198: C21.2 E16-36.1(P)
N$199: E16-37.1(P) E20.1
N$200: E16-38.1(P) E20.2
N$201: E16-39.1(P) E20.3
N$202: E16-40.1(P) E20.4
N$203: E16-65.1(P) E20.5
N$204: E16-66.1(P) E20.6
N$205: E16-67.1(P) E20.7
N$206: E16-68.1(P) E20.8
N$207: E16-69.1(P) E20.9
N$208: E16-70.1(P) E20.10
N$209: E16-71.1(P) E20.11
N$210: E16-72.1(P) E20.12
N$211: E16-73.1(P) E20.13
N$212: E16-74.1(P) E20.14
N$213: E16-75.1(P) E20.15
N$214: E16-76.1(P) E20.16
N$215: C20.1 E16-77.1(P)
N$216: C20.2 E16-78.1(P)
N$217: E16-79.1(P) E24.1
N$218: E16-80.1(P) E24.2
N$219: E16-81.1(P) E24.3
N$220: E16-82.1(P) E24.4
N$221: E16-83.1(P) E24.5
N$222: E16-84.1(P) E24.6
N$223: E16-85.1(P) E24.7
N$224: E16-86.1(P) E24.8
N$225: E16-87.1(P) E24.9
N$226: E16-88.1(P) E24.10
N$227: E16-89.1(P) E24.11
N$228: E16-90.1(P) E24.12
N$229: E16-91.1(P) E24.13
N$230: E16-92.1(P) E24.14
N$231: E16-93.1(P) E24.15
N$232: E16-94.1(P) E24.16
N$233: C24.1 E16-95.1(P)
N$234: C24.2 E16-96.1(P)
N$235: E16-97.1(P) E23.1
N$236: E16-98.1(P) E23.2
N$237: E16-99.1(P) E23.3
N$238: E16-100.1(P) E23.4
N$239: E16-101.1(P) E23.5
N$240: E16-102.1(P) E23.6
N$241: E16-103.1(P) E23.7
N$242: E16-104.1(P) E23.8
N$243: E16-105.1(P) E23.9
N$244: E16-106.1(P) E23.10
N$245: E16-107.1(P) E23.11
N$246: E16-108.1(P) E23.12
N$247: E16-109.1(P) E23.13
N$248: E16-110.1(P) E23.14
N$249: E16-111.1(P) E23.15
N$250: E16-112.1(P) E23.16
N$251: C23.1 E16-113.1(P)
N$252: C23.2 E16-114.1(P)
N$253: E16-115.1(P) E26.1
N$254: E16-116.1(P) E26.2
N$255: E16-117.1(P) E26.3
N$256: E16-118.1(P) E26.4
N$257: E16-119.1(P) E26.5
N$258: E16-120.1(P) E26.6
N$259: E16-121.1(P) E26.7
N$260: E16-122.1(P) E26.8
N$261: E16-123.1(P) E26.9
N$262: E16-124.1(P) E26.10
N$263: E16-125.1(P) E26.11
N$264: E16-126.1(P) E26.12
N$265: E16-127.1(P) E26.13
N$266: E16-128.1(P) E26.14
N$267: E16-129.1(P) E26.15
N$268: E16-130.1(P) E26.16
N$269: C25.1 E16-131.1(P)
N$270: C25.2 E16-132.1(P)
N$271: E16-133.1(P) E25.1
N$272: E16-134.1(P) E25.2
N$273: E16-135.1(P) E25.3
N$274: E16-136.1(P) E25.4
N$275: E16-137.1(P) E25.5
N$276: E16-138.1(P) E25.6
N$277: E16-139.1(P) E25.7
N$278: E16-140.1(P) E25.8
N$279: E16-141.1(P) E25.9
N$280: E16-142.1(P) E25.10
N$281: E16-143.1(P) E25.11
N$282: E16-144.1(P) E25.12
N$283: E16-145.1(P) E25.13
N$284: E16-146.1(P) E25.14
N$285: E16-147.1(P) E25.15
N$286: E16-148.1(P) E25.16
N$287: C26.1 E16-149.1(P)
N$288: C26.2 E16-150.1(P)
N$289: E16-151.1(P) E28.1
N$290: E16-152.1(P) E28.2
N$291: E16-153.1(P) E28.3
N$292: E16-154.1(P) E28.4
N$293: E16-155.1(P) E28.5
N$294: E16-156.1(P) E28.6
N$295: E16-157.1(P) E28.7
N$296: E16-158.1(P) E28.8
N$297: E16-159.1(P) E28.9
N$298: E16-160.1(P) E28.10
N$299: E16-161.1(P) E28.11
N$300: E16-162.1(P) E28.12
N$301: E16-163.1(P) E28.13
N$302: E16-164.1(P) E28.14
N$303: E16-165.1(P) E28.15
N$304: E16-166.1(P) E28.16
N$305: C27.1 E16-167.1(P)
N$306: C27.2 E16-168.1(P)
N$307: E16-169.1(P) E27.1
N$308: E16-170.1(P) E27.2
N$309: E16-171.1(P) E27.3
N$310: E16-172.1(P) E27.4
N$311: E16-173.1(P) E27.5
N$312: E16-174.1(P) E27.6
N$313: E16-175.1(P) E27.7
N$314: E16-176.1(P) E27.8
N$315: E16-177.1(P) E27.9
N$316: E16-178.1(P) E27.10
N$317: E16-179.1(P) E27.11
N$318: E16-180.1(P) E27.12
N$319: E16-181.1(P) E27.13
N$320: E16-182.1(P) E27.14
N$321: E16-183.1(P) E27.15
N$322: E16-184.1(P) E27.16
N$323: C28.1 E16-185.1(P)
N$324: C28.2 E16-186.1(P)
N$325: E16-187.1(P) E30.1
N$326: E16-188.1(P) E30.2
N$327: E16-189.1(P) E30.3
N$328: E16-190.1(P) E30.4
N$329: E16-191.1(P) E30.5
N$330: E16-192.1(P) E30.6
N$331: E16-193.1(P) E30.7
N$332: E16-194.1(P) E30.8
N$333: E16-195.1(P) E30.9
N$334: E16-196.1(P) E30.10
N$335: E16-197.1(P) E30.11
N$336: E16-198.1(P) E30.12
N$337: E16-199.1(P) E30.13
N$338: E16-200.1(P) E30.14
N$339: E16-201.1(P) E30.15
N$340: E16-202.1(P) E30.16
N$341: C29.1 E16-203.1(P)
N$342: C29.2 E16-204.1(P)
N$343: E16-205.1(P) E29.1
N$344: E16-206.1(P) E29.2
N$345: E16-207.1(P) E29.3
N$346: E16-208.1(P) E29.4
N$347: E16-209.1(P) E29.5
N$348: E16-210.1(P) E29.6
N$349: E16-211.1(P) E29.7
N$350: E16-212.1(P) E29.8
N$351: E16-213.1(P) E29.9
N$352: E16-214.1(P) E29.10
N$353: E16-215.1(P) E29.11
N$354: E16-216.1(P) E29.12
N$355: E16-217.1(P) E29.13
N$356: E16-218.1(P) E29.14
N$357: E16-219.1(P) E29.15
N$358: E16-220.1(P) E29.16
N$359: C32.1 E16-221.1(P)
N$360: C32.2 E16-222.1(P)
N$361: E16-223.1(P) E32.1
N$362: E16-224.1(P) E32.2
N$363: E16-225.1(P) E32.3
N$364: E16-226.1(P) E32.4
N$365: E16-227.1(P) E32.5
N$366: E16-228.1(P) E32.6
N$367: E16-229.1(P) E32.7
N$368: E16-230.1(P) E32.8
N$369: E16-231.1(P) E32.9
N$370: E16-232.1(P) E32.10
N$371: E16-233.1(P) E32.11
N$372: E16-234.1(P) E32.12
N$373: E16-235.1(P) E32.13
N$374: E16-236.1(P) E32.14
N$375: E16-237.1(P) E32.15
N$376: E16-238.1(P) E32.16
N$377: C31.1 E16-239.1(P)
N$378: C31.2 E16-240.1(P)
N$379: E16-241.1(P) E31.1
N$380: E16-242.1(P) E31.2
N$381: E16-243.1(P) E31.3
N$382: E16-244.1(P) E31.4
N$383: E16-245.1(P) E31.5
N$384: E16-246.1(P) E31.6
N$385: E16-247.1(P) E31.7
N$386: E16-248.1(P) E31.8
N$387: E16-249.1(P) E31.9
N$388: E16-250.1(P) E31.10
N$389: E16-251.1(P) E31.11
N$390: E16-252.1(P) E31.12
N$391: E16-253.1(P) E31.13
N$392: E16-254.1(P) E31.14
N$393: E16-255.1(P) E31.15
N$394: E16-256.1(P) E31.16
N$395: C34.1 E16-257.1(P)
N$396: C34.2 E16-258.1(P)
N$397: E16-259.1(P) E34.1
N$398: E16-260.1(P) E34.2
N$399: E16-261.1(P) E34.3
N$400: E16-262.1(P) E34.4
N$401: E16-263.1(P) E34.5
N$402: E16-264.1(P) E34.6
N$403: E16-265.1(P) E34.7
N$404: E16-266.1(P) E34.8
N$405: E16-267.1(P) E34.9
N$406: E16-268.1(P) E34.10
N$407: E16-269.1(P) E34.11
N$408: E16-270.1(P) E34.12
N$409: E16-271.1(P) E34.13
N$410: E16-272.1(P) E34.14
N$411: E16-273.1(P) E34.15
N$412: E16-274.1(P) E34.16
N$413: C30.1 E16-275.1(P)
N$414: C30.2 E16-276.1(P)
N$415: E16-277.1(P) E33.1
N$416: E16-278.1(P) E33.2
N$417: E16-279.1(P) E33.3
N$418: E16-280.1(P) E33.4
N$419: E16-281.1(P) E33.5
N$420: E16-282.1(P) E33.6
N$421: E16-283.1(P) E33.7
N$422: E16-284.1(P) E33.8
N$423: E16-285.1(P) E33.9
N$424: E16-286.1(P) E33.10
N$425: E16-287.1(P) E33.11
N$426: E16-288.1(P) E33.12
N$427: E16-289.1(P) E33.13
N$428: E16-290.1(P) E33.14
N$429: E16-291.1(P) E33.15
N$430: E16-292.1(P) E33.16
N$431: C33.1 E16-293.1(P)
N$432: C33.2 E16-294.1(P)
N$433: E16-295.1(P) E35.1
N$434: E16-296.1(P) E35.2
N$435: E16-297.1(P) E35.3
N$436: E16-298.1(P) E35.4
N$437: E16-299.1(P) E35.5
N$438: E16-300.1(P) E35.6
N$439: E16-301.1(P) E35.7
N$440: E16-302.1(P) E35.8
N$441: E16-303.1(P) E35.9
N$442: E16-304.1(P) E35.10
N$443: E16-305.1(P) E35.11
N$444: E16-306.1(P) E35.12
N$445: E16-307.1(P) E35.13
N$446: E16-308.1(P) E35.14
N$447: E16-309.1(P) E35.15
N$448: E16-310.1(P) E35.16
N$449: C35.1 E16-311.1(P)
N$450: C35.2 E16-312.1(P)
N$451: E16-313.1(P) E36.1
N$452: E16-314.1(P) E36.2
N$453: E16-315.1(P) E36.3
N$454: E16-316.1(P) E36.4
N$455: E16-317.1(P) E36.5
N$456: E16-318.1(P) E36.6
N$457: E16-319.1(P) E36.7
N$458: E16-320.1(P) E36.8
N$459: E16-321.1(P) E36.9
N$460: E16-322.1(P) E36.10
N$461: E16-323.1(P) E36.11
N$462: E16-324.1(P) E36.12
N$463: E16-325.1(P) E36.13
N$464: E16-326.1(P) E36.14
N$465: E16-327.1(P) E36.15
N$466: E16-328.1(P) E36.16
N$467: C36.1 E16-329.1(P)
N$468: C36.2 E16-330.1(P)
N$469: E16-331.1(P) E22.1
N$470: E16-332.1(P) E22.2
N$471: E16-333.1(P) E22.3
N$472: E16-334.1(P) E22.4
N$473: E16-335.1(P) E22.5
N$474: E16-336.1(P) E22.6
N$475: E16-337.1(P) E22.7
N$476: E16-338.1(P) E22.8
N$477: E16-339.1(P) E22.9
N$478: E16-340.1(P) E22.10
N$479: E16-341.1(P) E22.11
N$480: E16-342.1(P) E22.12
N$481: E16-343.1(P) E22.13
N$482: E16-344.1(P) E22.14
N$483: E16-345.1(P) E22.15
N$484: E16-346.1(P) E22.16
N$485: C22.1 E16-347.1(P)
N$486: C22.2 E16-348.1(P)

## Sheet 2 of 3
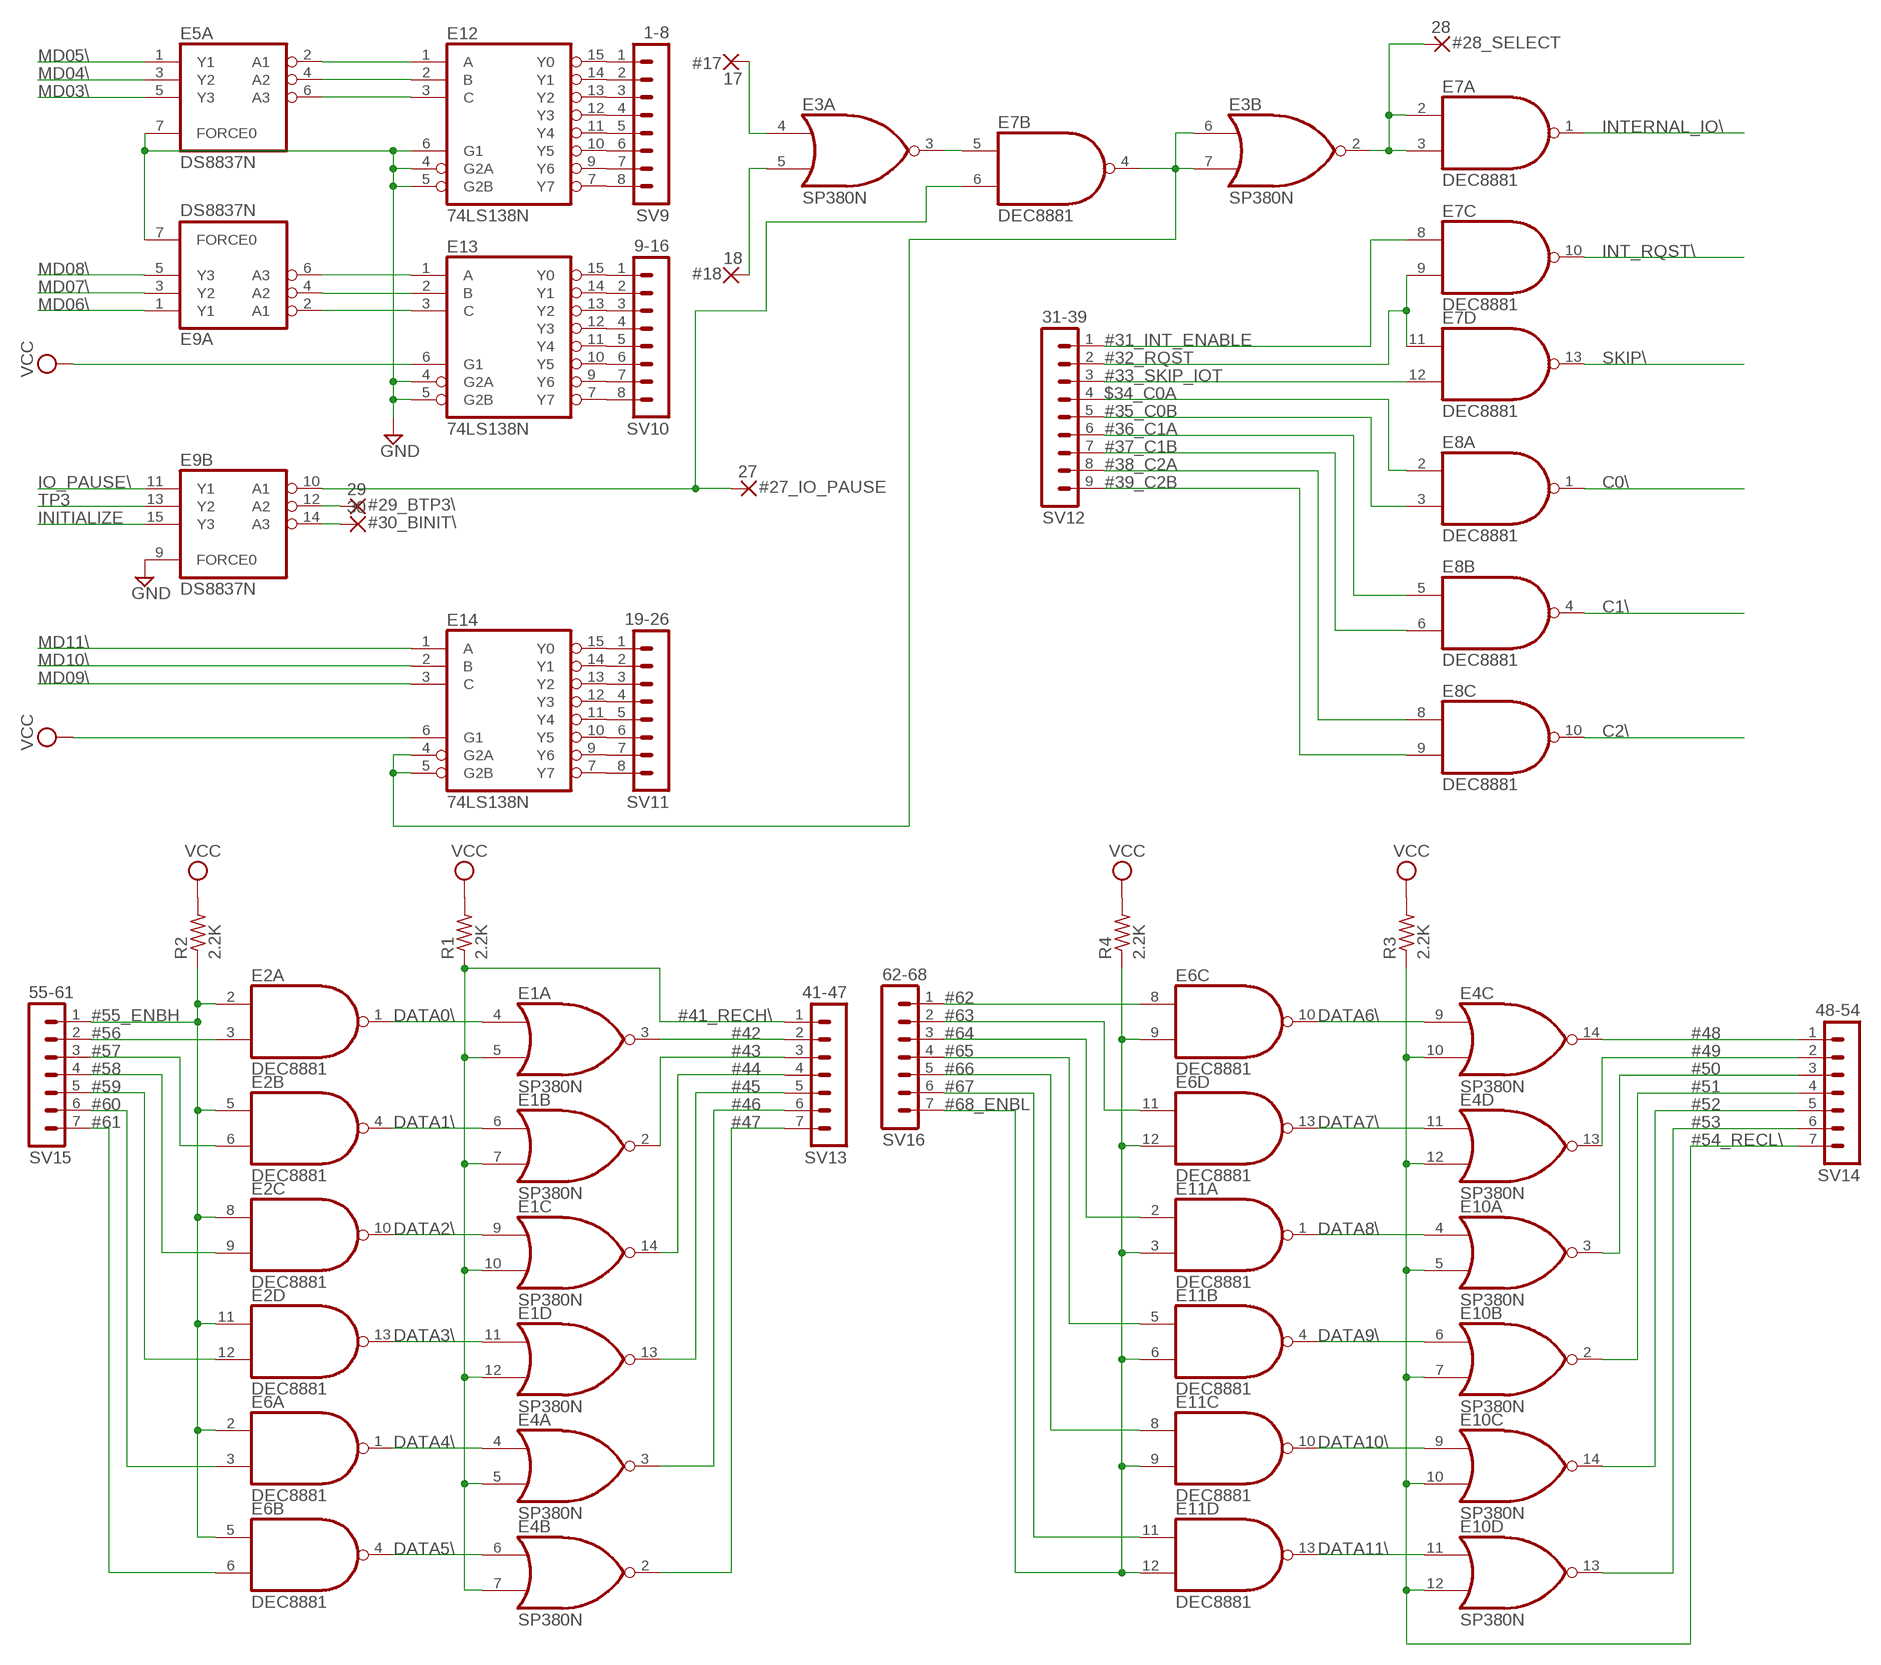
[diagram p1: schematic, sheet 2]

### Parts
#17  17  2,54/0,8  [2,54/0,8]
#18  18  2,54/0,8  [2,54/0,8]
#27_IO_PAUSE  27  2,54/0,8  [2,54/0,8]
#28_SELECT  28  2,54/0,8  [2,54/0,8]
#29_BTP3\  29  2,54/0,8  [2,54/0,8]
#30_BINIT\  30  2,54/0,8  [2,54/0,8]
E1  SP380N  [DIL14]
E2  DEC8881  7401N  [DIL14]
E3  SP380N  [DIL14]
E4  SP380N  [DIL14]
E5  DS8837N  [DIL16]
E6  DEC8881  7401N  [DIL14]
E7  DEC8881  7401N  [DIL14]
E8  DEC8881  7401N  [DIL14]
E9  DS8837N  [DIL16]
E10  SP380N  [DIL14]
E11  DEC8881  7401N  [DIL14]
E12  74LS138N  74HCT138N  [DIL16]
E13  74LS138N  74HCT138N  [DIL16]
E14  74LS138N  74HCT138N  [DIL16]
R1  2.2K  R-US_0207/10  [0207/10]
R2  2.2K  R-US_0207/10  [0207/10]
R3  2.2K  R-US_0207/10  [0207/10]
R4  2.2K  R-US_0207/10  [0207/10]
SV9  1-8  MA08-1  [MA08-1]
SV10  9-16  MA08-1  [MA08-1]
SV11  19-26  MA08-1  [MA08-1]
SV12  31-39  MA09-1  [MA09-1]
SV13  41-47  MA07-1  [MA07-1]
SV14  48-54  MA07-1  [MA07-1]
SV15  55-61  MA07-1  [MA07-1]
SV16  62-68  MA07-1  [MA07-1]

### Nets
#31_INT_ENABLE: E7.8(C:I0) SV12.1
#32_RQST: E7.9(C:I1) E7.11(D:I0) SV12.2
#33_SKIP_IOT: E7.12(D:I1) SV12.3
#35_C0B: E8.3(A:I1) SV12.5
#36_C1A: E8.5(B:I0) SV12.6
#37_C1B: E8.6(B:I1) SV12.7
#38_C2A: E8.8(C:I0) SV12.8
#39_C2B: E8.9(C:I1) SV12.9
#41_RECH\: E1.5(A:I1) E1.7(B:I1) E1.10(C:I1) E1.12(D:I1) E4.5(A:I1) E4.7(B:I1) R1.1 SV13.1
#42: E1.3(A:O) SV13.2
#43: E1.2(B:O) SV13.3
#44: E1.14(C:O) SV13.4
#45: E1.13(D:O) SV13.5
#46: E4.3(A:O) SV13.6
#47: E4.2(B:O) SV13.7
#48: E4.14(C:O) SV14.1
#49: E4.13(D:O) SV14.2
#50: E10.3(A:O) SV14.3
#51: E10.2(B:O) SV14.4
#52: E10.14(C:O) SV14.5
#53: E10.13(D:O) SV14.6
#54_RECL\: E4.10(C:I1) E4.12(D:I1) E10.5(A:I1) E10.7(B:I1) E10.10(C:I1) E10.12(D:I1) R3.1 SV14.7
#55_ENBH: E2.2(A:I0) E2.5(B:I0) E2.8(C:I0) E2.11(D:I0) E6.2(A:I0) E6.5(B:I0) R2.1 SV15.1
#56: E2.3(A:I1) SV15.2
#57: E2.6(B:I1) SV15.3
#58: E2.9(C:I1) SV15.4
#59: E2.12(D:I1) SV15.5
#60: E6.3(A:I1) SV15.6
#61: E6.6(B:I1) SV15.7
#62: E6.8(C:I0) SV16.1
#63: E6.11(D:I0) SV16.2
#64: E11.2(A:I0) SV16.3
#65: E11.5(B:I0) SV16.4
#66: E11.8(C:I0) SV16.5
#67: E11.11(D:I0) SV16.6
#68_ENBL: E6.9(C:I1) E6.12(D:I1) E11.3(A:I1) E11.6(B:I1) E11.9(C:I1) E11.12(D:I1) R4.1 SV16.7
$34_C0A: E8.2(A:I0) SV12.4
C0\: E8.1(A:O) ; also sheet 3
C1\: E8.4(B:O) ; also sheet 3
C2\: E8.10(C:O) ; also sheet 3
DATA0\: E1.4(A:I0) E2.1(A:O) ; also sheet 3
DATA1\: E1.6(B:I0) E2.4(B:O) ; also sheet 3
DATA2\: E1.9(C:I0) E2.10(C:O) ; also sheet 3
DATA3\: E1.11(D:I0) E2.13(D:O) ; also sheet 3
DATA4\: E4.4(A:I0) E6.1(A:O) ; also sheet 3
DATA5\: E4.6(B:I0) E6.4(B:O) ; also sheet 3
DATA6\: E4.9(C:I0) E6.10(C:O) ; also sheet 3
DATA7\: E4.11(D:I0) E6.13(D:O) ; also sheet 3
DATA8\: E10.4(A:I0) E11.1(A:O) ; also sheet 3
DATA9\: E10.6(B:I0) E11.4(B:O) ; also sheet 3
DATA10\: E10.9(C:I0) E11.10(C:O) ; also sheet 3
DATA11\: E10.11(D:I0) E11.13(D:O) ; also sheet 3
GND: E5.7(A:FORCE0) E9.7(A:FORCE0) E9.9(B:FORCE0) E12.4(G2A) E12.5(G2B) E12.6(G1) E13.4(G2A) E13.5(G2B) ; also sheet 1,3
INITIALIZE: E9.15(B:Y3) ; also sheet 3
INT_RQST\: E7.10(C:O) ; also sheet 3
INTERNAL_IO\: E7.1(A:O) ; also sheet 3
IO_PAUSE\: E9.11(B:Y1) ; also sheet 3
MD03\: E5.5(A:Y3) ; also sheet 3
MD04\: E5.3(A:Y2) ; also sheet 3
MD05\: E5.1(A:Y1) ; also sheet 3
MD06\: E9.1(A:Y1) ; also sheet 3
MD07\: E9.3(A:Y2) ; also sheet 3
MD08\: E9.5(A:Y3) ; also sheet 3
MD09\: E14.3(C) ; also sheet 3
MD10\: E14.2(B) ; also sheet 3
MD11\: E14.1(A) ; also sheet 3
N$487: E12.15(Y0) SV9.1
N$488: E12.14(Y1) SV9.2
N$489: E12.13(Y2) SV9.3
N$490: E12.12(Y3) SV9.4
N$491: E12.11(Y4) SV9.5
N$492: E12.10(Y5) SV9.6
N$493: E12.9(Y6) SV9.7
N$494: E12.7(Y7) SV9.8
N$495: E13.15(Y0) SV10.1
N$496: E13.14(Y1) SV10.2
N$497: E13.13(Y2) SV10.3
N$498: E13.12(Y3) SV10.4
N$499: E13.11(Y4) SV10.5
N$500: E13.10(Y5) SV10.6
N$501: E13.9(Y6) SV10.7
N$502: E13.7(Y7) SV10.8
N$503: E5.2(A:A1) E12.1(A)
N$504: E5.4(A:A2) E12.2(B)
N$505: E5.6(A:A3) E12.3(C)
N$506: E9.2(A:A1) E13.3(C)
N$507: E9.4(A:A2) E13.2(B)
N$508: E9.6(A:A3) E13.1(A)
N$509: E3.6(B:I0) E3.7(B:I1) E7.4(B:O) E14.4(G2A) E14.5(G2B)
N$510: #17.1(P) E3.4(A:I0)
N$511: #18.1(P) E3.5(A:I1)
N$512: E3.3(A:O) E7.5(B:I0)
N$513: E14.15(Y0) SV11.1
N$514: E14.14(Y1) SV11.2
N$515: E14.13(Y2) SV11.3
N$516: E14.12(Y3) SV11.4
N$517: E14.11(Y4) SV11.5
N$518: E14.10(Y5) SV11.6
N$519: E14.9(Y6) SV11.7
N$520: E14.7(Y7) SV11.8
N$521: #27_IO_PAUSE.1(P) E7.6(B:I1) E9.10(B:A1)
N$522: #28_SELECT.1(P) E3.2(B:O) E7.2(A:I0) E7.3(A:I1)
N$523: #30_BINIT\.1(P) E9.14(B:A3)
N$524: #29_BTP3\.1(P) E9.12(B:A2)
SKIP\: E7.13(D:O) ; also sheet 3
TP3: E9.13(B:Y2) ; also sheet 3
VCC: E13.6(G1) E14.6(G1) R1.2 R2.2 R3.2 R4.2 ; also sheet 3
Unconnected: E3.9(C:I0) E3.10(C:I1) E3.11(D:I0) E3.12(D:I1) E3.13(D:O) E3.14(C:O) E5.9(B:FORCE0) E5.10(B:A1) E5.11(B:Y1) E5.12(B:A2) E5.13(B:Y2) E5.14(B:A3) E5.15(B:Y3) E8.11(D:I0) E8.12(D:I1) E8.13(D:O)

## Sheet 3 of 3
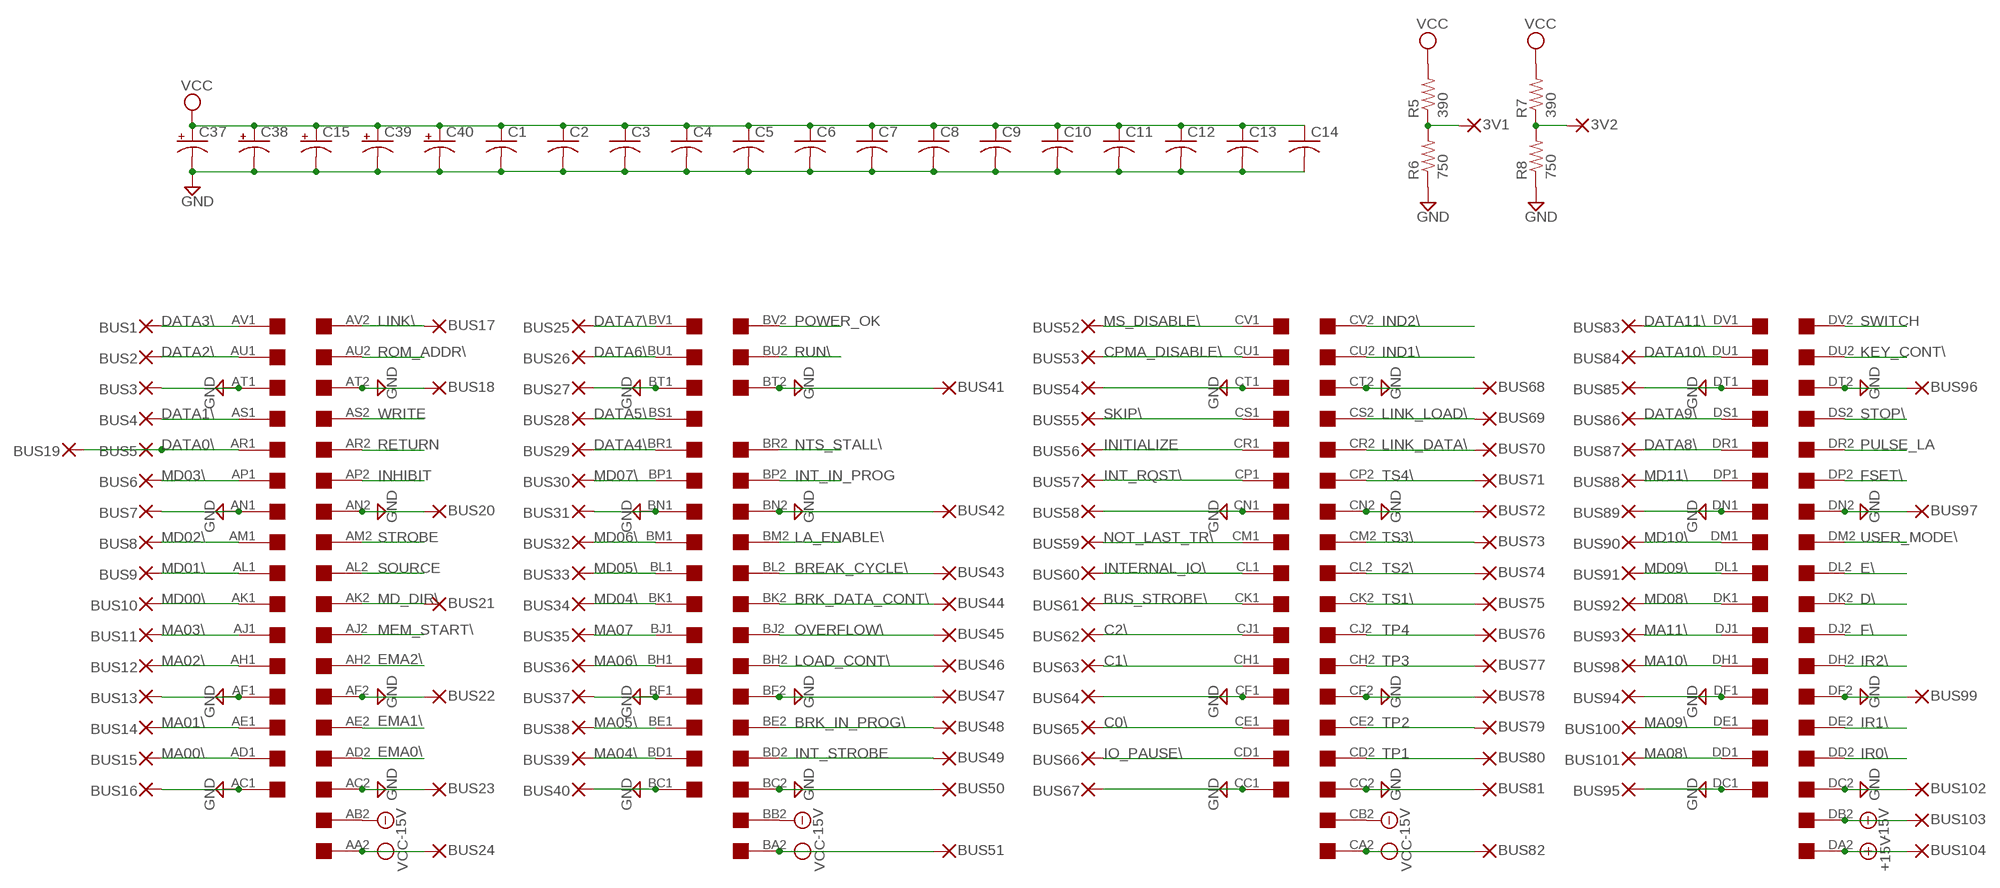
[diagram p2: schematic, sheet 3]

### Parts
3V1  2,54/0,8  [2,54/0,8]
3V2  2,54/0,8  [2,54/0,8]
BUS1  2,54/0,8  [2,54/0,8]
BUS2  2,54/0,8  [2,54/0,8]
BUS3  2,54/0,8  [2,54/0,8]
BUS4  2,54/0,8  [2,54/0,8]
BUS5  2,54/0,8  [2,54/0,8]
BUS6  2,54/0,8  [2,54/0,8]
BUS7  2,54/0,8  [2,54/0,8]
BUS8  2,54/0,8  [2,54/0,8]
BUS9  2,54/0,8  [2,54/0,8]
BUS10  2,54/0,8  [2,54/0,8]
BUS11  2,54/0,8  [2,54/0,8]
BUS12  2,54/0,8  [2,54/0,8]
BUS13  2,54/0,8  [2,54/0,8]
BUS14  2,54/0,8  [2,54/0,8]
BUS15  2,54/0,8  [2,54/0,8]
BUS16  2,54/0,8  [2,54/0,8]
BUS17  2,54/0,8  [2,54/0,8]
BUS18  2,54/0,8  [2,54/0,8]
BUS19  2,54/0,8  [2,54/0,8]
BUS20  2,54/0,8  [2,54/0,8]
BUS21  2,54/0,8  [2,54/0,8]
BUS22  2,54/0,8  [2,54/0,8]
BUS23  2,54/0,8  [2,54/0,8]
BUS24  2,54/0,8  [2,54/0,8]
BUS25  2,54/0,8  [2,54/0,8]
BUS26  2,54/0,8  [2,54/0,8]
BUS27  2,54/0,8  [2,54/0,8]
BUS28  2,54/0,8  [2,54/0,8]
BUS29  2,54/0,8  [2,54/0,8]
BUS30  2,54/0,8  [2,54/0,8]
BUS31  2,54/0,8  [2,54/0,8]
BUS32  2,54/0,8  [2,54/0,8]
BUS33  2,54/0,8  [2,54/0,8]
BUS34  2,54/0,8  [2,54/0,8]
BUS35  2,54/0,8  [2,54/0,8]
BUS36  2,54/0,8  [2,54/0,8]
BUS37  2,54/0,8  [2,54/0,8]
BUS38  2,54/0,8  [2,54/0,8]
BUS39  2,54/0,8  [2,54/0,8]
BUS40  2,54/0,8  [2,54/0,8]
BUS41  2,54/0,8  [2,54/0,8]
BUS42  2,54/0,8  [2,54/0,8]
BUS43  2,54/0,8  [2,54/0,8]
BUS44  2,54/0,8  [2,54/0,8]
BUS45  2,54/0,8  [2,54/0,8]
BUS46  2,54/0,8  [2,54/0,8]
BUS47  2,54/0,8  [2,54/0,8]
BUS48  2,54/0,8  [2,54/0,8]
BUS49  2,54/0,8  [2,54/0,8]
BUS50  2,54/0,8  [2,54/0,8]
BUS51  2,54/0,8  [2,54/0,8]
BUS52  2,54/0,8  [2,54/0,8]
BUS53  2,54/0,8  [2,54/0,8]
BUS54  2,54/0,8  [2,54/0,8]
BUS55  2,54/0,8  [2,54/0,8]
BUS56  2,54/0,8  [2,54/0,8]
BUS57  2,54/0,8  [2,54/0,8]
BUS58  2,54/0,8  [2,54/0,8]
BUS59  2,54/0,8  [2,54/0,8]
BUS60  2,54/0,8  [2,54/0,8]
BUS61  2,54/0,8  [2,54/0,8]
BUS62  2,54/0,8  [2,54/0,8]
BUS63  2,54/0,8  [2,54/0,8]
BUS64  2,54/0,8  [2,54/0,8]
BUS65  2,54/0,8  [2,54/0,8]
BUS66  2,54/0,8  [2,54/0,8]
BUS67  2,54/0,8  [2,54/0,8]
BUS68  2,54/0,8  [2,54/0,8]
BUS69  2,54/0,8  [2,54/0,8]
BUS70  2,54/0,8  [2,54/0,8]
BUS71  2,54/0,8  [2,54/0,8]
BUS72  2,54/0,8  [2,54/0,8]
BUS73  2,54/0,8  [2,54/0,8]
BUS74  2,54/0,8  [2,54/0,8]
BUS75  2,54/0,8  [2,54/0,8]
BUS76  2,54/0,8  [2,54/0,8]
BUS77  2,54/0,8  [2,54/0,8]
BUS78  2,54/0,8  [2,54/0,8]
BUS79  2,54/0,8  [2,54/0,8]
BUS80  2,54/0,8  [2,54/0,8]
BUS81  2,54/0,8  [2,54/0,8]
BUS82  2,54/0,8  [2,54/0,8]
BUS83  2,54/0,8  [2,54/0,8]
BUS84  2,54/0,8  [2,54/0,8]
BUS85  2,54/0,8  [2,54/0,8]
BUS86  2,54/0,8  [2,54/0,8]
BUS87  2,54/0,8  [2,54/0,8]
BUS88  2,54/0,8  [2,54/0,8]
BUS89  2,54/0,8  [2,54/0,8]
BUS90  2,54/0,8  [2,54/0,8]
BUS91  2,54/0,8  [2,54/0,8]
BUS92  2,54/0,8  [2,54/0,8]
BUS93  2,54/0,8  [2,54/0,8]
BUS94  2,54/0,8  [2,54/0,8]
BUS95  2,54/0,8  [2,54/0,8]
BUS96  2,54/0,8  [2,54/0,8]
BUS97  2,54/0,8  [2,54/0,8]
BUS98  2,54/0,8  [2,54/0,8]
BUS99  2,54/0,8  [2,54/0,8]
BUS100  2,54/0,8  [2,54/0,8]
BUS101  2,54/0,8  [2,54/0,8]
BUS102  2,54/0,8  [2,54/0,8]
BUS103  2,54/0,8  [2,54/0,8]
BUS104  2,54/0,8  [2,54/0,8]
C1  C-US075-032X103  [C075-032X103]
C2  C-US075-032X103  [C075-032X103]
C3  C-US075-032X103  [C075-032X103]
C4  C-US075-032X103  [C075-032X103]
C5  C-US075-032X103  [C075-032X103]
C6  C-US075-032X103  [C075-032X103]
C7  C-US075-032X103  [C075-032X103]
C8  C-US075-032X103  [C075-032X103]
C9  C-US075-032X103  [C075-032X103]
C10  C-US075-032X103  [C075-032X103]
C11  C-US075-032X103  [C075-032X103]
C12  C-US075-032X103  [C075-032X103]
C13  C-US075-032X103  [C075-032X103]
C14  C-US075-032X103  [C075-032X103]
C15  CPOL-USE22-6AXIAL  [E22-6]
C37  CPOL-USE22-6AXIAL  [E22-6]
C38  CPOL-USE22-6AXIAL  [E22-6]
C39  CPOL-USE22-6AXIAL  [E22-6]
C40  CPOL-USE22-6AXIAL  [E22-6]
R5  390  R-US_0207/10  [0207/10]
R6  750  R-US_0207/10  [0207/10]
R7  390  R-US_0207/10  [0207/10]
R8  750  R-US_0207/10  [0207/10]
U$2  QUAD  [EDGE-CON8]

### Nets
+15V: BUS104.1(P) U$2.DA2
-15V [supply]: BUS103.1(P) U$2.AB2 U$2.BB2 U$2.CB2 U$2.DB2
BREAK_CYCLE\: BUS43.1(P) U$2.BL2
BRK_DATA_CONT\: BUS44.1(P) U$2.BK2
BRK_IN_PROG\: BUS48.1(P) U$2.BE2
BUS_STROBE\: BUS61.1(P) U$2.CK1
C0\: BUS65.1(P) U$2.CE1 ; also sheet 2
C1\: BUS63.1(P) U$2.CH1 ; also sheet 2
C2\: BUS62.1(P) U$2.CJ1 ; also sheet 2
CPMA_DISABLE\: BUS53.1(P) U$2.CU1
D\: U$2.DK2
DATA0\: BUS5.1(P) BUS19.1(P) U$2.AR1 ; also sheet 2
DATA1\: BUS4.1(P) U$2.AS1 ; also sheet 2
DATA2\: BUS2.1(P) U$2.AU1 ; also sheet 2
DATA3\: BUS1.1(P) U$2.AV1 ; also sheet 2
DATA4\: BUS29.1(P) U$2.BR1 ; also sheet 2
DATA5\: BUS28.1(P) U$2.BS1 ; also sheet 2
DATA6\: BUS26.1(P) U$2.BU1 ; also sheet 2
DATA7\: BUS25.1(P) U$2.BV1 ; also sheet 2
DATA8\: BUS87.1(P) U$2.DR1 ; also sheet 2
DATA9\: BUS86.1(P) U$2.DS1 ; also sheet 2
DATA10\: BUS84.1(P) U$2.DU1 ; also sheet 2
DATA11\: BUS83.1(P) U$2.DV1 ; also sheet 2
E\: U$2.DL2
EMA0\: U$2.AD2
EMA1\: U$2.AE2
EMA2\: U$2.AH2
F\: U$2.DJ2
FSET\: U$2.DP2
GND: BUS3.1(P) BUS7.1(P) BUS13.1(P) BUS16.1(P) BUS18.1(P) BUS20.1(P) BUS22.1(P) BUS23.1(P) BUS27.1(P) BUS31.1(P) BUS37.1(P) BUS40.1(P) BUS41.1(P) BUS42.1(P) BUS47.1(P) BUS50.1(P) BUS54.1(P) BUS58.1(P) BUS64.1(P) BUS67.1(P) BUS68.1(P) BUS72.1(P) BUS78.1(P) BUS81.1(P) BUS85.1(P) BUS89.1(P) BUS94.1(P) BUS95.1(P) BUS96.1(P) BUS97.1(P) BUS99.1(P) BUS102.1(P) C1.2 C2.2 C3.2 C4.2 C5.2 C6.2 C7.2 C8.2 C9.2 C10.2 C11.2 C12.2 C13.2 C14.2 C15.- C37.- C38.- C39.- C40.- R6.1 R8.1 U$2.AC1 U$2.AC2 U$2.AF1 U$2.AF2 U$2.AN1 U$2.AN2 U$2.AT1 U$2.AT2 U$2.BC1 U$2.BC2 U$2.BF1 U$2.BF2 U$2.BN1 U$2.BN2 U$2.BT1 U$2.BT2 U$2.CC1 U$2.CC2 U$2.CF1 U$2.CF2 U$2.CN1 U$2.CN2 U$2.CT1 U$2.CT2 U$2.DC1 U$2.DC2 U$2.DF1 U$2.DF2 U$2.DN1 U$2.DN2 U$2.DT1 U$2.DT2 ; also sheet 1,2
IND1\: U$2.CU2
IND2\: U$2.CV2
INHIBIT: U$2.AP2
INITIALIZE: BUS56.1(P) U$2.CR1 ; also sheet 2
INT_IN_PROG: U$2.BP2
INT_RQST\: BUS57.1(P) U$2.CP1 ; also sheet 2
INT_STROBE: BUS49.1(P) U$2.BD2
INTERNAL_IO\: BUS60.1(P) U$2.CL1 ; also sheet 2
IO_PAUSE\: BUS66.1(P) U$2.CD1 ; also sheet 2
IR0\: U$2.DD2
IR1\: U$2.DE2
IR2\: U$2.DH2
KEY_CONT\: U$2.DU2
LA_ENABLE\: U$2.BM2
LINK\: BUS17.1(P) U$2.AV2
LINK_DATA\: BUS70.1(P) U$2.CR2
LINK_LOAD\: BUS69.1(P) U$2.CS2
LOAD_CONT\: BUS46.1(P) U$2.BH2
MA00\: BUS15.1(P) U$2.AD1
MA01\: BUS14.1(P) U$2.AE1
MA02\: BUS12.1(P) U$2.AH1
MA03\: BUS11.1(P) U$2.AJ1
MA04\: BUS39.1(P) U$2.BD1
MA05\: BUS38.1(P) U$2.BE1
MA06\: BUS36.1(P) U$2.BH1
MA07: BUS35.1(P) U$2.BJ1
MA08\: BUS101.1(P) U$2.DD1
MA09\: BUS100.1(P) U$2.DE1
MA10\: BUS98.1(P) U$2.DH1
MA11\: BUS93.1(P) U$2.DJ1
MD00\: BUS10.1(P) U$2.AK1
MD01\: BUS9.1(P) U$2.AL1
MD02\: BUS8.1(P) U$2.AM1
MD03\: BUS6.1(P) U$2.AP1 ; also sheet 2
MD04\: BUS34.1(P) U$2.BK1 ; also sheet 2
MD05\: BUS33.1(P) U$2.BL1 ; also sheet 2
MD06\: BUS32.1(P) U$2.BM1 ; also sheet 2
MD07\: BUS30.1(P) U$2.BP1 ; also sheet 2
MD08\: BUS92.1(P) U$2.DK1 ; also sheet 2
MD09\: BUS91.1(P) U$2.DL1 ; also sheet 2
MD10\: BUS90.1(P) U$2.DM1 ; also sheet 2
MD11\: BUS88.1(P) U$2.DP1 ; also sheet 2
MD_DIR\: BUS21.1(P) U$2.AK2
MEM_START\: U$2.AJ2
MS_DISABLE\: BUS52.1(P) U$2.CV1
N$525: 3V1.1(P) R5.1 R6.2
N$526: 3V2.1(P) R7.1 R8.2
NOT_LAST_TR\: BUS59.1(P) U$2.CM1
NTS_STALL\: U$2.BR2
OVERFLOW\: BUS45.1(P) U$2.BJ2
POWER_OK: U$2.BV2
PULSE_LA: U$2.DR2
RETURN: U$2.AR2
ROM_ADDR\: U$2.AU2
RUN\: U$2.BU2
SKIP\: BUS55.1(P) U$2.CS1 ; also sheet 2
SOURCE: U$2.AL2
STOP\: U$2.DS2
STROBE: U$2.AM2
SWITCH: U$2.DV2
TP1: BUS80.1(P) U$2.CD2
TP2: BUS79.1(P) U$2.CE2
TP3: BUS77.1(P) U$2.CH2 ; also sheet 2
TP4: BUS76.1(P) U$2.CJ2
TS1\: BUS75.1(P) U$2.CK2
TS2\: BUS74.1(P) U$2.CL2
TS3\: BUS73.1(P) U$2.CM2
TS4\: BUS71.1(P) U$2.CP2
USER_MODE\: U$2.DM2
VCC: BUS24.1(P) BUS51.1(P) BUS82.1(P) C1.1 C2.1 C3.1 C4.1 C5.1 C6.1 C7.1 C8.1 C9.1 C10.1 C11.1 C12.1 C13.1 C14.1 C15.+ C37.+ C38.+ C39.+ C40.+ R5.2 R7.2 U$2.AA2 U$2.BA2 U$2.CA2 ; also sheet 2
WRITE: U$2.AS2
Unconnected: U$2.AA1 U$2.AB1 U$2.BA1 U$2.BB1 U$2.BS2 U$2.CA1 U$2.CB1 U$2.DA1 U$2.DB1

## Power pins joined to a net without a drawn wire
GND: E1.1(P:GND) E2.7(P:GND) E3.1(P:GND) E4.1(P:GND) E5.8(P:GND) E6.7(P:GND) E7.7(P:GND) E8.7(P:GND) E9.8(P:GND) E10.1(P:GND) E11.7(P:GND) E12.8(GND) E13.8(GND) E14.8(GND)
VCC: E1.8(P:VCC) E2.14(P:VCC) E3.8(P:VCC) E4.8(P:VCC) E5.16(P:VCC) E6.14(P:VCC) E7.14(P:VCC) E8.14(P:VCC) E9.16(P:VCC) E10.8(P:VCC) E11.14(P:VCC) E12.16(VCC) E13.16(VCC) E14.16(VCC)

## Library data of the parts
3V1 3V2 #17 #18 #27_IO_PAUSE #28_SELECT #29_BTP3\ #30_BINIT\ BUS1-BUS104 E16-19-E16-40 E16-65-E16-348 FA1 FA2 FB1 FB2 FC1 FC2 FD1 FD2 FE1 FE2 FF1 FF2 FH1 FH2 FJ1 FJ2 FK1 FK2 FL1 FL2 FM1 FM2 FN1 FN2 FP1 FP2 FR1 FR2 FS1 FS2 FT1 FT2 FU1 FU2 FV1 FV2 HA1 HA2 HB1 HB2 HC1 HC2 HD1 HD2 HE1 HE2 HF1 HF2 HH1 HH2 HJ1 HJ2 HK1 HK2 HL1 HL2 HM1 HM2 HN1 HN2 HP1 HP2 HR1 HR2 HS1 HS2 HT1 HT2 HU1 HU2 HV1 HV2 J1BB J1BB1 J1D J1D1 J1DD J1DD1 J1F J1F1 J1FF J1FF1 J1J J1J1 J1JJ J1JJ1 J1L J1L1 J1LL J1LL1 J1N J1N1 J1NN J1NN1 J1R J1R1 J1RR J1RR1 J1T J1T1 J1TT J1TT1 J1V J1V1 J1X J1X1 J1Z J1Z1 = wirepad:2,54/0,8: THROUGH-HOLE PAD
C1-C14 C16-C36 = rcl:C-US: CAPACITOR, American symbol
C1-1 C1-2 E16-1-E16-16 E17-1-E17-24 E18-1-E18-24 E19-1-E19-24 = wirepad:1,6/0,8: THROUGH-HOLE PAD
C15 C37-C40 = rcl:CPOL-US: POLARIZED CAPACITOR, American symbol
E1 E3 E4 E10 = dec-con:SP380: Quad NOR gate (use 8640)
E2 E6-E8 E11 = 74xx-jameco:74*01: Quad 2-input NAND gate, open collector
E5 E9 = dec-con:DS8837: Hex inverting LINE RECEIVER
E12-E14 = 74xx-eu:74*138: 3-line to 8-line DECODER/DEMULTIPLEXER
E16-E36 = ic-package:DIL16: Dual In Line
F H = dec-con:SINGLE: Single-Height DEC board
J1 = dec-con:DEC40PIN: PIN HEADER
R1-R8 = rcl:R-US_: RESISTOR, American symbol
SV1-SV6 = con-lstb:MA12-1: PIN HEADER
SV7-SV11 = con-lstb:MA08-1: PIN HEADER
SV12 = con-lstb:MA09-1: PIN HEADER
SV13-SV16 = con-lstb:MA07-1: PIN HEADER
U$2 = dec-con:QUAD: Quad-Height DEC board

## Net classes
1 supply: width 0.762 mm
